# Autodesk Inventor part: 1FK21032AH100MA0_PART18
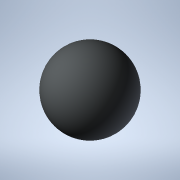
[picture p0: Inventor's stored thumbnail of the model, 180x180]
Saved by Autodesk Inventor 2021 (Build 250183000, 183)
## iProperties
Created: 2025-04
Part Number: 1FK21032AH100MA0_PART18
Material: Generic
Catalog Web Link: www.3dfindit.com
Description: -Servo synchronous motor
Document SubType Name: Modeling
Designer: psAdmin
Mass: 0.113097 g
Surface Area: 1.13097 cm^2
Volume: 0.113097 cm^3
Density: 1 g/cm^3
Appearance: PSOLRGB-212-217-219
Category: PARTsolutions
Title: 1FK21032AH100MA0_PART18
Author: Cadenas PARTsolutions
Comments: Servo synchronous motor
Sending System: PARTsolutions
Preprocessor: ST-DEVELOPER v19.3
PSOL_IDENT_0: {$CADENAS_DATA/23d-libs/siemens_ag/_cat_/12/33/1fk21032ah100ma0.prj},216 {VTYP=3D},{NB=1FK21032AH100
PSOL_IDENT_1: MA0_PART18},{LINA=1FK21032AH100MA0_PART18},{NN=1FK21032AH100MA0_PART18},{NOPRJ=TRUE},{DATE=19.08.202
PSOL_IDENT_2: 5 14:00:27},{GEOMDATE=30.07.2025 02:02:58},{VERSION=},{LINEID=10},{WBVAR=},{WBNUMERIC=}  {NB=1FK2103
PSOL_IDENT_3: 2AH100MA0_PART18},{LINA=1FK21032AH100MA0_PART18},{KT=DUMMY},{PREVIEW=../../../_pool_/d3/78/p_d211_xx
PSOL_IDENT_4: _00934j.png},{DESCSHORT=SIMOTICS S-1FK2 HD, SINAMICS S210 3AC 400V-480V, 0.59 Nm, 4500 rpm},{DESCLON
PSOL_IDENT_5: G=SIMOTICS S-1FK2 HD servo motor M0=0.64 Nm; PN = 0.28 kW at nN=4500 rpm (380-480 V); PN = 0.167 kW
PSOL_IDENT_6: at nN=2500 rpm (200-240 V); with holding brake; degree of protection IP64; cylindrical shaft D14 x 3
PSOL_IDENT_7: 0 mm; absolute encoder 22-bit + 12-bit multiturn (encoder AM22DQC); with OCC interface; plug size M1
PSOL_IDENT_8: 7, rotatable; SIMOTICS S-1FK2 servomotorfor a wide range of uses in industrial environments. SIMOTIC
PSOL_IDENT_9: S S‑1FK2 servomotors are compact synchronous motors with a high dynamic performance that set themsel
PSOL_IDENT_10: ves apart as a result of their high power density, degree of protection and overload capability. The
PSOL_IDENT_11: motors are available in two variants: as High Dynamic variant (highest dynamic performance as a res
PSOL_IDENT_12: ult of the low intrinsic moment of inertia for applications demanding a high dynamic performance wit
PSOL_IDENT_13: h low moved masses) - and as Compact variant (precise and stable closed-loop control for medium up t
PSOL_IDENT_14: o large moved masses as a result of a medium intrinsic moment of inertia). SIMOTICSS‑1FK2 servomotor
PSOL_IDENT_15: s fully exploit their strengths in a system with the SINAMICSS210 frequency converter and simple con
PSOL_IDENT_16: nection using the one cable connection (OCC). Advantages include the short control and positioning t
PSOL_IDENT_17: imes, fast and precise correction of disturbing quantities as well as stable control with a high dyn
PSOL_IDENT_18: amic performance. The servo motors can be configured to address a wide range of requirements. For ex
PSOL_IDENT_19: ample with and without holding brake, IP64 or IP65 degree of protection, singleturn or multiturn abs
PSOL_IDENT_20: olute encoders - to name just a few. Further, the servomotors are available in different shaft heigh
PSOL_IDENT_21: ts extending from 20 to 100. A shaft sealing ring is available to achieve an IP65 degree of protecti
PSOL_IDENT_22: on and for subsequent mounting at the motor or as spare part. SIMOTICS - the optimum motor for each
PSOL_IDENT_23: and every motion control application.},{INTNO=195125315563},{SUPPLIERALTNO=1FK2103-2AH10-0MA0},{MANU
PSOL_IDENT_24: ID=1FK21032AH100MA0},{MANUNAME=Siemens},{MANUTYPEDESC=SYNCHRONOUS MOTOR 1FK2 HD 0,64 NM},{AAU732=SIM
PSOL_IDENT_25: OTICS},{AAO057=S-1FK2},{AAU734=SIMOTICS S-1FK2 HD servo motor M0=0.64 Nm; PN = 0.28 kW at nN=4500 rp
PSOL_IDENT_26: m (380-480 V); PN = 0.167 kW at nN=2500 rpm (200-240 V); with holding brake; degree of protection IP
PSOL_IDENT_27: 64; cylindrical shaft D14 x 30 mm; absolute encoder 22-bit + 12-bit multiturn (encoder AM22DQC); wit
PSOL_IDENT_28: h OCC interface; plug size M17, rotatable;},{AAW338=SYNCHRONOUS MOTOR 1FK2 HD 0,64 NM},{AAO742=SIMOT
PSOL_IDENT_29: ICS},{AAO663=4034106444723},{NOCUPEROU=1},{PRICEQUANTITY=1},{QUANTITYMIN=1},{QUANTITYINT=1},{CTN=850
PSOL_IDENT_30: 15100},{COO=RO},{AAO676=1FK2103-2AH10-0MA0},{AAO677=Siemens AG},{ORDERUNIT=C62},{CONTENTUNIT=C62}
NB: 1FK21032AH100MA0_PART18
NT: Servo synchronous motor
NBSYN: $MANUID._PART18
LINA: 1FK21032AH100MA0_PART18
CATALOG: SIEMENS
PREVIEW: ../../../_pool_/d3/78/p_d211_xx_00934j.png
DESCSHORT: SIMOTICS S-1FK2 HD, SINAMICS S210 3AC 400V-480V, 0.59 Nm, 4500 rpm
DESCLONG: SIMOTICS S-1FK2 HD servo motor M0=0.64 Nm; PN = 0.28 kW at nN=4500 rpm (380-480 V); PN = 0.167 kW at nN=2500 rpm (200-240 V); with holding brake; degree of prot
INTNO: 195125315563
SUPPLIERALTNO: 1FK2103-2AH10-0MA0
MANUID: 1FK21032AH100MA0
MANUNAME: Siemens
MANUTYPEDESC: SYNCHRONOUS MOTOR 1FK2 HD 0,64 NM
AAU732: SIMOTICS
AAO057: S-1FK2
AAU734: SIMOTICS S-1FK2 HD servo motor M0=0.64 Nm; PN = 0.28 kW at nN=4500 rpm (380-480 V); PN = 0.167 kW at nN=2500 rpm (200-240 V); with holding brake; degree of prot
AAW338: SYNCHRONOUS MOTOR 1FK2 HD 0,64 NM
AAO742: SIMOTICS
AAO663: 4034106444723.0
NOCUPEROU: 1
PRICEQUANTITY: 1
QUANTITYMIN: 1
QUANTITYINT: 1
CTN: 85015100
COO: RO
ARTICLENO: 1FK21032AH100MA0_PART18
BOMINFO: 1FK21032AH100MA0_PART18
CREATOR: CADENAS GmbH
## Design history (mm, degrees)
feature "2025_04_17_15_06_16_0705"
body "Solid1"
